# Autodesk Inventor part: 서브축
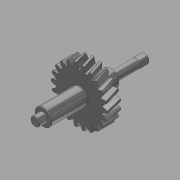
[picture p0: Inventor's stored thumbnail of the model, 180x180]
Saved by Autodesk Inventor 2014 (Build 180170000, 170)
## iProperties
Created: 2017-11
Part Number: 서브축
Material: 강철, 탄소
Document SubType Name: Modeling
Designer: mduedu
Categories: <?xml version="1.0" encoding="UTF-16"?> <MemberInstance><Categories><FamilyTemplate><FamilyTemplateParameter ValueType="xs:double" Id="1" ObjectReferenceKey="da
Density: 7.87 g/cm^3
Appearance: 반광택
Mass: 233.4 g
Surface Area: 98.1276 cm^2
Volume: 29.657 cm^3
CustomPartVersion: 1
Author: mduedu
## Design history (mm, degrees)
sketch "Sketch1"
  geometry: C1 r 24.776 at (0, 0)
  constraints: 1 centre point
  dimensions: "d0" = 49.55215 diameter of C1 (= da_da)
extrude "Extrusion1" new body sketch "Sketch1" distance "d1" = 12 (= da_b); taper "d2" = 0 deg
workplane "Work Plane2"
sketch "Sketch2"
  geometry: C1 r 24.776 at (0, 0) reference; C2 r 22.776 at (0, 0)
  constraints: 1 centre point, 1 coincident
  dimensions: "d3" = 45.55215 diameter of C2 (= da_dw)
feature "피치 지름" sketch "Sketch2" dims "d4" = 10, "d5" = 0
workplane "Work Plane8"
workplane "Work Plane9"
feature "스퍼 기어" dims "da_b" = 12, "da_d" = 45.55215, "da_aw" = 54.86964, "da_da" = 49.55215, "da_df" = 40.55215, "da_dw" = 45.55215, angle "da_beta" = 15 deg, "da_lefttooth" = 10, "da_righttooth" = 0
sketch "스케치3"
  geometry: C1 r 7.5 at (0, 0); 1 further point
  constraints: 1 centre point, 1 coincident
  dimensions: "d49" = 15 diameter of C1
extrude "돌출2" join sketch "스케치3" distance "d50" = 32; taper "d51" = 0 deg
sketch "스케치4"
  geometry: C1 r 4 at (0, 0); 1 further point
  constraints: 1 centre point, 1 coincident
  dimensions: "d52" = 8 diameter of C1
extrude "돌출3" join sketch "스케치4" distance "d53" = 7; taper "d54" = 0 deg
sketch "스케치5"
  geometry: C1 r 7.5 at (0, 0); 1 further point
  constraints: 1 centre point, 1 coincident
  dimensions: "d55" = 15 diameter of C1
extrude "돌출4" join sketch "스케치5" distance "d56" = 16; taper "d57" = 0 deg
sketch "스케치6"
  geometry: C1 r 4 at (0, 0); 1 further point
  constraints: 1 centre point, 1 coincident
  dimensions: "d58" = 8 diameter of C1
extrude "돌출5" join sketch "스케치6" distance "d59" = 30; taper "d60" = 0 deg
chamfer "모따기1" distance "d61" = 0.5; stored, may be unused: second distance "d62" = 2, angle "d63" = 45 deg
fillet "모깎기1" dims "d64" = 0.5
sketch "스케치7"
  geometry: L1 (-3.25, -3.25)-(3.25, -3.25); L2 (3.25, -3.25)-(3.25, 3.25); L3 (3.25, 3.25)-(-3.25, 3.25); L4 (-3.25, 3.25)-(-3.25, -3.25); L5 (-3.25, -3.25)-(3.25, 3.25); L6 (3.25, -3.25)-(-3.25, 3.25); L7 (-5, -5)-(5, -5); L8 (5, -5)-(5, 5); L9 (5, 5)-(-5, 5); L10 (-5, 5)-(-5, -5); L11 (-5, -5)-(5, 5); L12 (5, -5)-(-5, 5); 1 further point
  constraints: 24 end point, 4 midpoint, 4 parallel, 2 horizontal, 2 perpendicular
  dimensions: "d65" = 6.5 distance of L3.end L2.end; "d66" = 6.5 distance of L2.end L1.end; "d67" = 10 distance of L9.end L8.end; "d68" = 10 distance of L8.end L7.end
extrude "돌출6" cut sketch "스케치7" distance "d69" = 8; taper "d70" = 0 deg
body "Solid1"
body "Srf1"
other parameters: "d16" = 54.86964 (= da_aw), "d17" = 0, "d34" = 1.428 (computed from da_z), "d39" = 0, "d41" = 0, "d43" = 54.86964 (= da_aw), "d46" = 54.86964 (= da_aw), "d47" = 0, "d48" = 0
